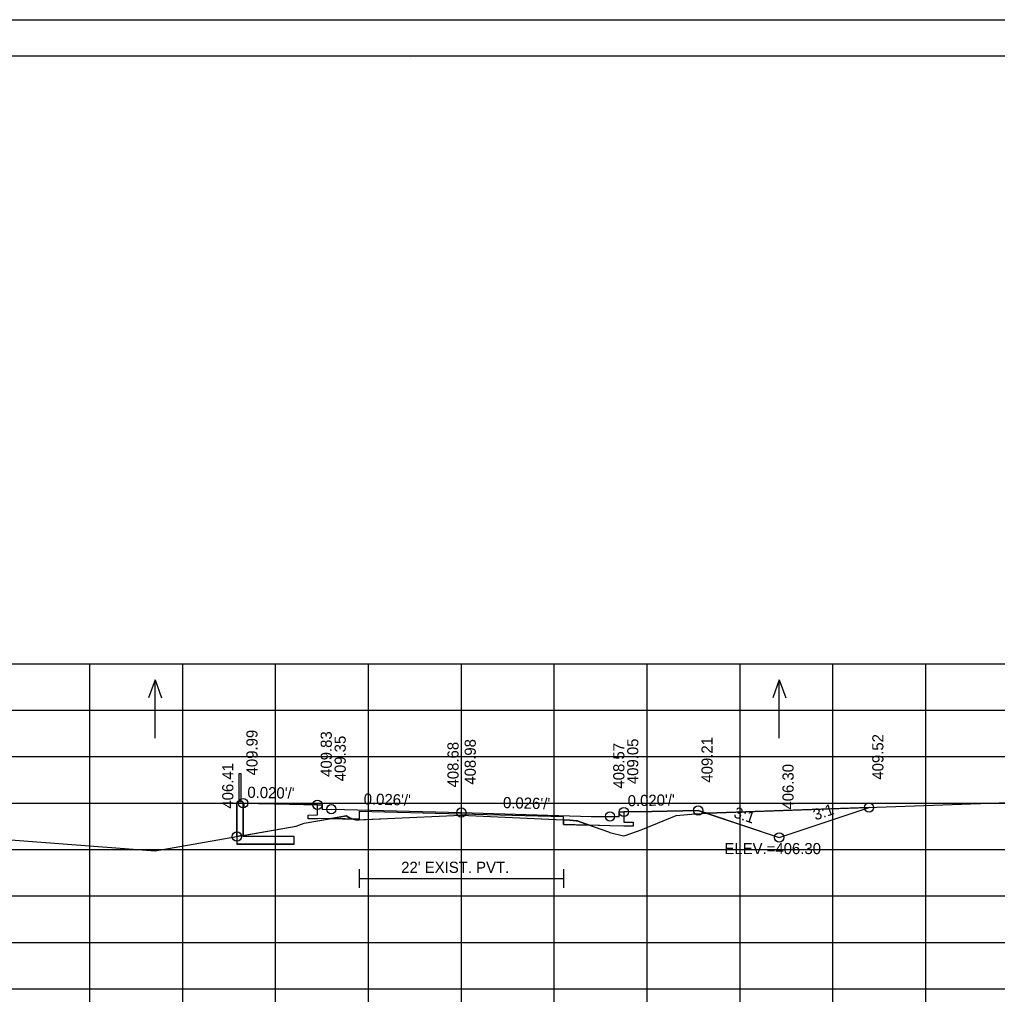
# Model space of a CAD drawing. Extents: x -37291014 to -37290680, y -936053 to -933067.
# Drawn here: x -37290890.6 to -37290785.4, y -935946.4 to -935840 of the extents above; entities that cross this region are included whole.
import ezdxf

# ---------------------------------------------------------------- set-up
doc = ezdxf.new("R2010")
doc.units = 0
for name, color, linetype in [('Default', 7, 'Continuous'), ('R_Alt Surface', 7, 'Continuous'), ('R_Axis', 7, 'Continuous'), ('R_Border', 7, 'Continuous'), ('R_Contours', 7, 'Continuous'), ('R_Exist Surface', 7, 'Continuous'), ('R_Fin Surface', 7, 'Continuous'), ('R_Grid', 7, 'Continuous'), ('R_No Plot', 7, 'Continuous'), ('R_Water', 7, 'Continuous'), ('R_Water Annot', 7, 'Continuous'), ('R_Xsect Elev', 7, 'Continuous'), ('R_Xsect Slope', 7, 'Continuous')]:
    doc.layers.add(name, color=color, linetype=linetype)

msp = doc.modelspace()

# ---------------------------------------------------------------- linework, layer by layer
at = {"layer": 'Default'}
for p, q in [((-37290867.02, -935924.15), (-37290867.02, -935921.15)), ((-37290867.02, -935921.15), (-37290866.85, -935921.15)), ((-37290866.85, -935921.15), (-37290866.85, -935924.15)), ((-37290867.21, -935924.17), (-37290867.27, -935924.23)), ((-37290867.27, -935924.23), (-37290867.27, -935928.75)), ((-37290866.66, -935924.15), (-37290867.21, -935924.15)), ((-37290867.21, -935924.15), (-37290867.21, -935924.17)), ((-37290866.66, -935924.17), (-37290867.21, -935924.17)), ((-37290866.66, -935924.17), (-37290866.66, -935924.15)), ((-37290866.6, -935924.23), (-37290866.66, -935924.17)), ((-37290866.6, -935927.92), (-37290866.6, -935924.23)), ((-37290861.1, -935928.75), (-37290867.27, -935928.75)), ((-37290861.1, -935927.92), (-37290866.6, -935927.92)), ((-37290861.1, -935928.75), (-37290861.1, -935927.92))]:
    msp.add_line(p, q, dxfattribs=at)
msp.add_lwpolyline([(-37290866.52, -935924.84), (-37290866.6, -935924.84), (-37290866.6, -935924.34), (-37290866.52, -935924.34), (-37290866.52, -935924.84)], dxfattribs=at)
at = {"layer": 'R_Alt Surface'}
for points in [[(-37290825.6, -935925.28), (-37290825.6, -935926.37), (-37290824.59, -935926.39), (-37290824.6, -935926.81), (-37290825.6, -935926.79), (-37290827.1, -935926.76), (-37290832.1, -935926.63), (-37290832.1, -935925.8), (-37290843.1, -935925.51), (-37290854.1, -935925.22), (-37290854.1, -935926.05), (-37290857.1, -935925.98), (-37290858.6, -935926.01), (-37290859.6, -935926.03), (-37290859.61, -935925.61), (-37290858.6, -935925.59), (-37290858.6, -935924.5)], [(-37290854.1, -935931.44), (-37290854.1, -935933.44)], [(-37290832.1, -935931.44), (-37290832.1, -935933.44)], [(-37290854.1, -935932.44), (-37290832.1, -935932.44)]]:
    msp.add_lwpolyline(points, dxfattribs=at)
at = {"layer": 'R_Axis'}
for p, q in [((-37290993.1, -935944.32), (-37290693.1, -935944.32)), ((-37290883.1, -935945.72), (-37290883.1, -935944.32)), ((-37290873.1, -935945.72), (-37290873.1, -935944.32)), ((-37290863.1, -935945.72), (-37290863.1, -935944.32)), ((-37290853.1, -935945.72), (-37290853.1, -935944.32)), ((-37290843.1, -935945.72), (-37290843.1, -935944.32)), ((-37290833.1, -935945.72), (-37290833.1, -935944.32)), ((-37290823.1, -935945.72), (-37290823.1, -935944.32)), ((-37290813.1, -935945.72), (-37290813.1, -935944.32)), ((-37290803.1, -935945.72), (-37290803.1, -935944.32)), ((-37290793.1, -935945.72), (-37290793.1, -935944.32))]:
    msp.add_line(p, q, dxfattribs=at)
at = {"layer": 'R_Border'}
for p, q in [((-37291001.1, -935843.86), (-37290684.92, -935843.86)), ((-37290848.58, -935844.12), (-37290848.58, -935844.12)), ((-37290848.58, -935844.12), (-37290848.58, -935844.12))]:
    msp.add_line(p, q, dxfattribs=at)
at = {"layer": 'R_Contours'}
for p, q in [((-37290866.6, -935924.84), (-37290866.6, -935927.8)), ((-37290816.69, -935925.42), (-37290817.6, -935925.12)), ((-37290816.69, -935925.42), (-37290808.88, -935928.02)), ((-37290808.88, -935928.02), (-37290799.21, -935924.8)), ((-37290857.07, -935925.98), (-37290854.74, -935926.04)), ((-37290854.1, -935926.05), (-37290854.74, -935926.04)), ((-37290854.1, -935926.05), (-37290854.1, -935926.13)), ((-37290854.1, -935926.05), (-37290854.1, -935926.13)), ((-37290854.1, -935926.13), (-37290854.1, -935926.05)), ((-37290832.1, -935926.12), (-37290832.1, -935925.8)), ((-37290832.1, -935926.12), (-37290832.1, -935926.63)), ((-37290832.1, -935926.63), (-37290829.32, -935926.7)), ((-37290866.6, -935927.92), (-37290866.6, -935927.8)), ((-37290867.27, -935928.75), (-37290861.1, -935928.75)), ((-37290861.1, -935927.92), (-37290866.6, -935927.92)), ((-37290861.1, -935928.75), (-37290861.1, -935927.92))]:
    msp.add_line(p, q, dxfattribs=at)
for points in [[(-37290866.52, -935924.34), (-37290866.52, -935924.84), (-37290866.6, -935924.84)], [(-37290858.6, -935924.5), (-37290861.6, -935924.44), (-37290866.52, -935924.34)], [(-37290857.1, -935925.98), (-37290858.6, -935926.01), (-37290859.6, -935926.03), (-37290859.61, -935925.61), (-37290858.6, -935925.59), (-37290858.6, -935924.5)], [(-37290854.74, -935926.04), (-37290855.21, -935925.86), (-37290855.48, -935925.7), (-37290857.07, -935925.98)], [(-37290832.1, -935925.8), (-37290843.1, -935925.51), (-37290854.1, -935925.22), (-37290854.1, -935926.05)], [(-37290854.1, -935926.13), (-37290851.06, -935925.97), (-37290843.13, -935925.64), (-37290835.21, -935925.98), (-37290832.1, -935926.12)], [(-37290825.6, -935925.28), (-37290825.6, -935926.37), (-37290824.59, -935926.39), (-37290824.6, -935926.81), (-37290825.6, -935926.79), (-37290827.1, -935926.76), (-37290829.32, -935926.7)], [(-37290829.32, -935926.7), (-37290827.26, -935927.43), (-37290827.11, -935927.48), (-37290825.63, -935927.85), (-37290825.45, -935927.8), (-37290823.73, -935927.19), (-37290823.38, -935927.05), (-37290819.97, -935925.65), (-37290817.93, -935925.49), (-37290816.69, -935925.42)], [(-37290817.6, -935925.12), (-37290822.6, -935925.22), (-37290825.6, -935925.28)], [(-37290799.21, -935924.8), (-37290816.59, -935925.42), (-37290816.69, -935925.42)], [(-37290866.6, -935927.8), (-37290860.89, -935926.81), (-37290860.04, -935926.49), (-37290857.1, -935925.98)], [(-37290857.1, -935925.98), (-37290857.1, -935925.98)], [(-37290854.74, -935926.04), (-37290854.45, -935926.14), (-37290854.1, -935926.13)], [(-37290829.32, -935926.7), (-37290830.36, -935926.33), (-37290830.6, -935926.25), (-37290830.69, -935926.24), (-37290831.43, -935926.15), (-37290832.1, -935926.12)], [(-37290866.6, -935927.8), (-37290866.65, -935927.81), (-37290867.27, -935927.92)], [(-37290867.27, -935927.92), (-37290867.27, -935927.92), (-37290867.27, -935928.75)]]:
    msp.add_lwpolyline(points, dxfattribs=at)
at = {"layer": 'R_Exist Surface'}
msp.add_lwpolyline([(-37290900.63, -935927.6), (-37290876.07, -935929.48), (-37290866.65, -935927.81), (-37290860.89, -935926.81), (-37290860.04, -935926.49), (-37290855.48, -935925.7), (-37290855.21, -935925.86), (-37290854.45, -935926.14), (-37290851.06, -935925.97), (-37290843.13, -935925.64), (-37290835.21, -935925.98), (-37290831.43, -935926.15), (-37290830.69, -935926.24), (-37290830.6, -935926.25), (-37290830.36, -935926.33), (-37290827.26, -935927.43), (-37290827.11, -935927.48), (-37290825.63, -935927.85), (-37290825.45, -935927.8), (-37290823.73, -935927.19), (-37290823.38, -935927.05), (-37290819.97, -935925.65), (-37290817.93, -935925.49), (-37290816.59, -935925.42), (-37290754.79, -935923.22)], dxfattribs=at)
at = {"layer": 'R_Fin Surface'}
msp.add_lwpolyline([(-37290867.27, -935927.92), (-37290867.27, -935924.34), (-37290866.6, -935924.34), (-37290861.6, -935924.44), (-37290858.6, -935924.5), (-37290858.1, -935924.5), (-37290858.1, -935925), (-37290857.1, -935924.98), (-37290843.1, -935925.34), (-37290829.11, -935925.76), (-37290829.11, -935925.76), (-37290829.1, -935925.76), (-37290829.1, -935925.76), (-37290829.1, -935925.76), (-37290829.1, -935925.76), (-37290827.1, -935925.76), (-37290826.1, -935925.78), (-37290826.1, -935925.28), (-37290825.6, -935925.28), (-37290822.6, -935925.22), (-37290817.6, -935925.12), (-37290808.88, -935928.02), (-37290799.21, -935924.8)], dxfattribs=at)
at = {"layer": 'R_Grid'}
for p, q in [((-37290993.1, -935909.32), (-37290693.1, -935909.32)), ((-37290883.1, -935944.32), (-37290883.1, -935909.32)), ((-37290873.1, -935944.32), (-37290873.1, -935909.32)), ((-37290863.1, -935944.32), (-37290863.1, -935909.32)), ((-37290853.1, -935944.32), (-37290853.1, -935909.32)), ((-37290843.1, -935944.32), (-37290843.1, -935909.32)), ((-37290833.1, -935944.32), (-37290833.1, -935909.32)), ((-37290823.1, -935944.32), (-37290823.1, -935909.32)), ((-37290813.1, -935944.32), (-37290813.1, -935909.32)), ((-37290803.1, -935944.32), (-37290803.1, -935909.32)), ((-37290793.1, -935944.32), (-37290793.1, -935909.32)), ((-37290993.1, -935914.32), (-37290693.1, -935914.32)), ((-37290993.1, -935919.32), (-37290693.1, -935919.32)), ((-37290993.1, -935924.32), (-37290693.1, -935924.32)), ((-37290993.1, -935929.32), (-37290693.1, -935929.32)), ((-37290993.1, -935934.32), (-37290693.1, -935934.32)), ((-37290993.1, -935939.32), (-37290693.1, -935939.32)), ((-37290993.1, -935944.32), (-37290693.1, -935944.32))]:
    msp.add_line(p, q, dxfattribs=at)
at = {"layer": 'R_No Plot'}
msp.add_line((-37291013.5, -935839.97), (-37290680.17, -935839.97), dxfattribs=at)
for points in [[(-37291013.51, -935839.97), (-37290680.17, -935839.97), (-37290680.17, -936053.31), (-37291013.51, -936053.31)], [(-37290767.18, -935843.86), (-37290747.56, -935843.86), (-37290747.56, -935853.74), (-37290731.45, -935853.74), (-37290708.25, -935853.74), (-37290708.25, -935878.08), (-37290684.92, -935878.08), (-37290684.92, -936049.32), (-37291001.1, -936049.32), (-37291001.1, -935843.86)]]:
    msp.add_lwpolyline(points, close=True, dxfattribs=at)
for centre in [(-37290866.6, -935924.34), (-37290858.6, -935924.5), (-37290857.1, -935924.98), (-37290817.6, -935925.12), (-37290799.21, -935924.8), (-37290843.1, -935925.34), (-37290827.1, -935925.76), (-37290827.1, -935925.76), (-37290825.6, -935925.28), (-37290867.27, -935927.92), (-37290808.88, -935928.02)]:
    msp.add_circle(centre, 0.5, dxfattribs=at)
at = {"layer": 'R_Water Annot'}
for p, q in [((-37290876.07, -935911.06), (-37290876.77, -935912.98)), ((-37290876.07, -935917.34), (-37290876.07, -935911.06)), ((-37290876.07, -935911.06), (-37290875.37, -935912.98)), ((-37290808.88, -935911.06), (-37290809.58, -935912.98)), ((-37290808.88, -935917.34), (-37290808.88, -935911.06)), ((-37290808.88, -935911.06), (-37290808.18, -935912.98))]:
    msp.add_line(p, q, dxfattribs=at)
at = {"layer": 'R_Xsect Elev'}
msp.add_line((-37290843.1, -935925.64), (-37290843.1, -935915.64), dxfattribs=at)

# ---------------------------------------------------------------- texts
at = {"layer": 'R_Water'}
msp.add_text("22' EXIST. PVT.", height=1.2, dxfattribs=at).set_placement((-37290849.58, -935931.84))
at = {"layer": 'R_Xsect Elev'}
for s, p in [('409.99', (-37290865.05, -935921.34)), ('409.83', (-37290857.05, -935921.5)), ('409.35', (-37290855.55, -935921.98)), ('409.52', (-37290797.66, -935921.8)), ('408.68', (-37290843.4, -935922.64)), ('408.98', (-37290841.55, -935922.34)), ('408.57', (-37290825.55, -935922.76)), ('409.05', (-37290824.05, -935922.28)), ('409.21', (-37290816.05, -935922.12)), ('406.41', (-37290867.65, -935924.92)), ('406.30', (-37290807.33, -935925.02))]:
    msp.add_text(s, height=1.2, rotation=90, dxfattribs=at).set_placement(p)
msp.add_text('ELEV.=406.30', height=1.2, dxfattribs=at).set_placement((-37290814.78, -935929.82))
at = {"layer": 'R_Xsect Slope'}
for s, rotation, p in [("0.020'/'", 358.8542, (-37290866.15, -935923.75)), ("0.026'/'", 358.5106, (-37290853.63, -935924.47)), ("0.020'/'", 1.1458, (-37290825.18, -935924.67)), ("0.026'/'", 358.5106, (-37290838.63, -935924.86)), ('3:1', 18.4332, (-37290804.99, -935926.2)), ('3:1', 341.5668, (-37290813.87, -935925.83))]:
    msp.add_text(s, height=1.2, rotation=rotation, dxfattribs=at).set_placement(p)

doc.saveas('drawing.dxf')
